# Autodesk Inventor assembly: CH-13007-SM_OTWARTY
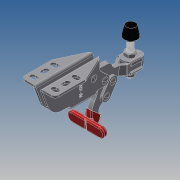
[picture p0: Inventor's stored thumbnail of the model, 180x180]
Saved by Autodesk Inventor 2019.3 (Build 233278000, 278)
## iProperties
Company: Microsoft
Created: 2017-11
Part Number: CH-13007-SM_OTWARTY
Material: Ogólny
Description: STEP AP203
Document SubType Name: Assembly
Designer: Admin
Sending System: SolidWorks 2015
Preprocessor: SwSTEP 2.0
Title: CH-13007-SM.STEP
Author: Windows
Revision Number: ÈÎºÎ
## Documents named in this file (7)
- E:\SERWER_ZAPAS\MODELE brakujace\brakujące stepy_08012019\CH-13007-SM\CH-13007-SM_OTWARTY.iam
- E:\SERWER_ZAPAS\MODELE brakujace\brakujące stepy_08012019\CH-13007-SM\13007-SMµ××ù.ipt
- E:\SERWER_ZAPAS\MODELE brakujace\brakujące stepy_08012019\CH-13007-SM\CH-13007-02 U-BAR.ipt
- E:\SERWER_ZAPAS\MODELE brakujace\brakujące stepy_08012019\CH-13007-SM\CH-13007-04 CONNECTING-PLATE.ipt
- E:\SERWER_ZAPAS\MODELE brakujace\brakujące stepy_08012019\CH-13007-SM\CH-13007-03 T-HANDLE.ipt
- E:\SERWER_ZAPAS\MODELE brakujace\brakujące stepy_08012019\CH-13007-SM\CH-13007-05 .ipt
- E:\SERWER_ZAPAS\MODELE brakujace\brakujące stepy_08012019\CH-13007-SM\400.iam
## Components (10 placed, 10 different names)
1. 13007-SMµ××ù_1 — Zestawiające:15, Zestawiające:16, Zestawiające:17, Zestawiające:18, Zestawiające:21
2. CH-13007-02 U-BAR_2 — Zestawiające:1, Kątowe:1, Zestawiające:2, Zestawiające:3, Zestawiające:4, Zestawiające:5, Zestawiające:6, Zestawiające:7, Zestawiające:19, Zestawiające:21
3. CH-13007-04 CONNECTING-PLATE_3 — Zestawiające:6, Zestawiające:7, Zestawiające:8, Zestawiające:9, Zestawiające:10, Zestawiające:11, Zestawiające:12, Zestawiające:13, Zestawiające:14
4. CH-13007-04 CONNECTING-PLATE_4 — Zestawiające:4, Zestawiające:5, Zestawiające:8
5. CH-13007-03 T-HANDLE_5 — Zestawiające:11, Zestawiające:12, Zestawiające:20
6. CH-13007-05 _6 — Zestawiające:9, Zestawiające:10
7. CH-13007-05 _7 — Zestawiające:13, Zestawiające:14
8. CH-13007-05 _8 — Zestawiające:16, Zestawiające:17, Zestawiające:20
9. CH-13007-05 _9 — Zestawiające:15, Zestawiające:18, Zestawiające:19
10. 400_10 [sub-assembly] — Równoległe:1, Zestawiające:2, Zestawiające:3
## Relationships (23: Mate 21, Angle 1, Flush 1)
- Zestawiające:1 [Mate]: CH-13007-02 U-BAR_2
- Kątowe:1 [Angle]: CH-13007-02 U-BAR_2
- Równoległe:1 [Flush]: 400_10
- Zestawiające:2 [Mate]: CH-13007-02 U-BAR_2 ↔ 400_10
- Zestawiające:3 [Mate]: CH-13007-02 U-BAR_2 ↔ 400_10
- Zestawiające:4 [Mate]: CH-13007-02 U-BAR_2 ↔ CH-13007-04 CONNECTING-PLATE_4
- Zestawiające:5 [Mate]: CH-13007-02 U-BAR_2 ↔ CH-13007-04 CONNECTING-PLATE_4
- Zestawiające:6 [Mate]: CH-13007-02 U-BAR_2 ↔ CH-13007-04 CONNECTING-PLATE_3
- Zestawiające:7 [Mate]: CH-13007-02 U-BAR_2 ↔ CH-13007-04 CONNECTING-PLATE_3
- Zestawiające:8 [Mate]: CH-13007-04 CONNECTING-PLATE_3 ↔ CH-13007-04 CONNECTING-PLATE_4
- Zestawiające:9 [Mate]: CH-13007-04 CONNECTING-PLATE_3 ↔ CH-13007-05 _6
- Zestawiające:10 [Mate]: CH-13007-04 CONNECTING-PLATE_3 ↔ CH-13007-05 _6
- Zestawiające:11 [Mate]: CH-13007-04 CONNECTING-PLATE_3 ↔ CH-13007-03 T-HANDLE_5
- Zestawiające:12 [Mate]: CH-13007-04 CONNECTING-PLATE_3 ↔ CH-13007-03 T-HANDLE_5
- Zestawiające:13 [Mate]: CH-13007-04 CONNECTING-PLATE_3 ↔ CH-13007-05 _7
- Zestawiające:14 [Mate]: CH-13007-04 CONNECTING-PLATE_3 ↔ CH-13007-05 _7
- Zestawiające:15 [Mate]: 13007-SMµ××ù_1 ↔ CH-13007-05 _9
- Zestawiające:16 [Mate]: 13007-SMµ××ù_1 ↔ CH-13007-05 _8
- Zestawiające:17 [Mate]: 13007-SMµ××ù_1 ↔ CH-13007-05 _8
- Zestawiające:18 [Mate]: 13007-SMµ××ù_1 ↔ CH-13007-05 _9
- Zestawiające:19 [Mate]: CH-13007-02 U-BAR_2 ↔ CH-13007-05 _9
- Zestawiające:20 [Mate]: CH-13007-03 T-HANDLE_5 ↔ CH-13007-05 _8
- Zestawiające:21 [Mate]: 13007-SMµ××ù_1 ↔ CH-13007-02 U-BAR_2
